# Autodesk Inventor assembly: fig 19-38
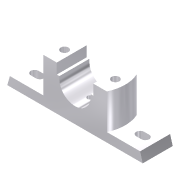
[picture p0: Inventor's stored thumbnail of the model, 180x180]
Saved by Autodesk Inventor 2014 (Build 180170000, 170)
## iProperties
Shininess: 64.0
Length Units: 11269
Angle Units: 11279
Time Units: 11290
Mass Units: 11283
Length Display Precision: 3
Angle Display Precision: 2
Compacted: True
Created: 2003-06
Part Number: fig 19-38
Document SubType Name: Assembly
Designer: Owner
Density: 0.0
Volumn: 0.0
Area: 0.0
PropertySet Name: Model Information
Control State: 0
Master: False
Checked Out: False
Author: Owner
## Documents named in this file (2)
- E:\APS\c19partfiles\fig 19-38.iam
- E:\APS\Autodesk Inventor 2014-Project\Inventor_2014_Manuscript\c09_inv_2014\Plummer Block\Casting.ipt
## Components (1 placed, 1 different names)
1. Casting:1
